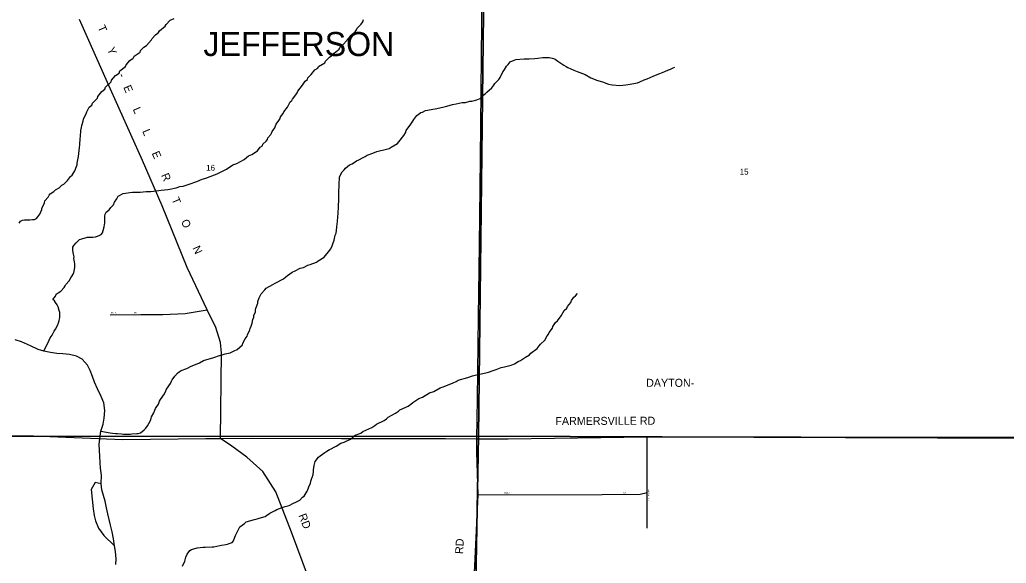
# Model space of a CAD drawing. Extents: x 1312308 to 1684953, y 460642 to 865172.
# Drawn here: x 1455224 to 1464469, y 623895 to 628989 of the extents above; entities that cross this region are included whole.
import ezdxf

# ---------------------------------------------------------------- set-up
doc = ezdxf.new("R2010")
doc.units = 0
for name, color, linetype in [('GM_X_County_Road', 7, 'Continuous'), ('GM_X_County_Road_Text', 7, 'Continuous'), ('GM_X_Minor_River', 7, 'Continuous'), ('GM_X_Section', 7, 'Continuous'), ('GM_X_Section_Text', 7, 'Continuous'), ('GM_X_Township_Subdivision', 7, 'Continuous'), ('GM_X_Township_Subdivision_Text', 7, 'Continuous'), ('GM_X_Township_Text', 7, 'Continuous')]:
    doc.layers.add(name, color=color, linetype=linetype)

msp = doc.modelspace()

# ---------------------------------------------------------------- linework, layer by layer
at = {"layer": 'GM_X_County_Road'}
for points in [[(1459508.2, 625062.6), (1459512.2, 625434.5), (1459523.6, 626204.4), (1459532.8, 626876), (1459543.2, 627687.9), (1459552.6, 628638), (1459557, 629271.5), (1459570.7, 630143.3), (1459577.4, 631061.3), (1459621.4, 632060.4)], [(1458997.4, 620898.3), (1458819.1, 621371.3), (1458583.5, 622020.5), (1458321, 622722.5), (1457980.8, 623622.7), (1457769.3, 624187), (1457623.6, 624565.4), (1457501.7, 624754.6), (1457352.5, 624890.3), (1457210.6, 624993.7), (1457105.9, 625064), (1457115.4, 625863), (1457105.7, 625964.9), (1457061.5, 626103.5), (1456978.7, 626269), (1456791.8, 626665.5), (1456559.2, 627244.6), (1456374.5, 627669.9), (1456047.3, 628401.2), (1455783.7, 628992)], [(1454210.5, 625100.4), (1455352.9, 625087.9), (1456190.5, 625056.2), (1456967.8, 625063.2), (1457105.9, 625064), (1457396.6, 625065.8), (1458239.8, 625063.3), (1459213.3, 625064), (1459508.2, 625062.6), (1459800.2, 625061.2), (1461104, 625081.4), (1462543.4, 625079.9), (1464684.9, 625077), (1465945, 625083.6)], [(1459463.9, 622759.1), (1459465.3, 622835.9), (1459485.3, 623806.4), (1459520.8, 624537.8), (1459507, 624939.2), (1459508.2, 625062.6)]]:
    msp.add_lwpolyline(points, dxfattribs=at)
at = {"layer": 'GM_X_Minor_River'}
for points in [[(1455219.1, 627082), (1455231.6, 627099.8), (1455250, 627111.4), (1455268.2, 627112.9), (1455284.3, 627112.6), (1455318.5, 627113.7), (1455344.7, 627115.1), (1455362.9, 627116.7), (1455381.3, 627126.3), (1455393.7, 627142), (1455410.5, 627165.8), (1455421.1, 627189.6), (1455429.7, 627209.5), (1455432.1, 627223.6), (1455449.1, 627257.3), (1455455.5, 627273.3), (1455460, 627291.2), (1455489.1, 627326.7), (1455499.6, 627344.6), (1455508, 627358.4), (1455542.8, 627379.7), (1455559.3, 627395.4), (1455592, 627412.7), (1455618.8, 627438.2), (1455637.1, 627447.8), (1455672.3, 627483.1), (1455699.4, 627520.7), (1455715.8, 627532.3), (1455741, 627573.9), (1455754.1, 627613.8), (1455760.6, 627629.8), (1455763, 627645.8), (1455772.3, 627691.8), (1455774.7, 627707.8), (1455780.1, 627762), (1455784.9, 627792), (1455785.5, 627816.2), (1455791.1, 627876.3), (1455791.6, 627894.4), (1455797.1, 627950.6), (1455803.8, 627978.6), (1455806.3, 627998.7), (1455819.5, 628038.5), (1455822, 628060.6), (1455847.4, 628108.2), (1455851.9, 628124.2), (1455875.1, 628167.9), (1455897.8, 628187.4), (1455904.3, 628205.4), (1455951.8, 628252.5), (1455956.2, 628268.4), (1455991.7, 628315.8), (1456020.4, 628337.2), (1456026.9, 628357.2), (1456080.5, 628406.2), (1456085, 628422.1), (1456122.4, 628467.4), (1456155.1, 628488.8), (1456161.7, 628508.7), (1456215.1, 628551.6), (1456221.5, 628565.6), (1456256.8, 628606.9), (1456287.6, 628628.3), (1456296.1, 628646.2), (1456351.4, 628685), (1456355.8, 628699), (1456386.9, 628732.4), (1456411.4, 628747.9), (1456459, 628799), (1456465.4, 628812.9), (1456496.5, 628848.4), (1456525.2, 628867.8), (1456533.7, 628885.7), (1456587.2, 628928.6), (1456595.6, 628944.4), (1456634.9, 628983.7), (1456669.5, 629000.9)], [(1457613.3, 627976.4), (1457621.8, 627994.3), (1457626.2, 628010.3), (1457653.3, 628045.8), (1457663.8, 628063.7), (1457668.3, 628079.6), (1457693.3, 628111.2), (1457699.7, 628127.1), (1457733, 628170.5), (1457758.4, 628218.2), (1457774.9, 628231.9), (1457779.3, 628245.8), (1457812.5, 628285.2), (1457825, 628303), (1457829.5, 628319), (1457873.2, 628374.2), (1457898.3, 628413.8), (1457918.9, 628429.4), (1457923.2, 628443.4), (1457956.3, 628474.7), (1457989.6, 628518.2), (1458016.2, 628533.6), (1458024.6, 628549.5), (1458081.9, 628586.3), (1458088.3, 628600.2), (1458125.5, 628637.5), (1458158.3, 628658.8), (1458168.8, 628676.6), (1458218, 628713.6), (1458222.4, 628727.6), (1458251.3, 628753), (1458292.6, 628796.2), (1458311.3, 628817.9), (1458319.9, 628837.8), (1458367.2, 628876.8), (1458379.7, 628894.6), (1458386.1, 628908.5), (1458423.3, 628945.8), (1458438, 628969.6), (1458446.6, 628991.5)], [(1458214.2, 627316.2), (1458213.1, 627352.4), (1458215.9, 627458.9), (1458218.9, 627499.1), (1458221.4, 627517.1), (1458246.7, 627562.8), (1458263.3, 627582.5), (1458275.8, 627596.2), (1458314.9, 627629.5), (1458339.3, 627638.9), (1458378.2, 627666.1), (1458402.6, 627675.6), (1458441.4, 627698.8), (1458461.8, 627706.3), (1458478.2, 627718), (1458533, 627736.7), (1458569.7, 627753.9), (1458608.2, 627763), (1458622.3, 627766.7), (1458685.2, 627783.3), (1458703.6, 627794.9), (1458762.8, 627829.6), (1458777.3, 627845.3), (1458823.1, 627902.5), (1458837.9, 627930.3), (1458846.5, 627950.2), (1458890.3, 628009.5), (1458907.1, 628037.2), (1458915.6, 628055.1), (1458944.7, 628090.6), (1458959, 628100.3), (1458983.6, 628117.8), (1458997.9, 628123.5), (1459026.4, 628136.8), (1459044.6, 628140.4), (1459095.2, 628151.2), (1459115.4, 628154.8), (1459188.3, 628169.1), (1459212.6, 628176.5), (1459226.8, 628180.2), (1459279.5, 628195), (1459313.9, 628200.2), (1459370.6, 628212.9), (1459400.8, 628214.1), (1459441.3, 628225.2), (1459461.5, 628226.7), (1459506.1, 628237.7), (1459538.6, 628251), (1459563.5, 628278.5), (1459590.1, 628296), (1459600.5, 628309.8), (1459647.9, 628350.9), (1459666.6, 628374.5), (1459677.1, 628390.4), (1459714.3, 628427.7), (1459724.8, 628447.5), (1459750.4, 628501.2), (1459764.8, 628514.9), (1459786, 628554.6), (1459800.4, 628568.3), (1459819.2, 628594), (1459857.9, 628611.1), (1459872.1, 628616.8), (1459950.7, 628620.9), (1459981, 628622.2), (1459999.1, 628623.8), (1460049.5, 628626.6), (1460079.8, 628629.8), (1460126.2, 628634.7), (1460150.3, 628634.1), (1460184.6, 628635.3), (1460200.6, 628632.9), (1460224.6, 628624.3), (1460240.5, 628619.9), (1460266.2, 628601.2), (1460286, 628588.6), (1460323.6, 628561.6), (1460343.4, 628551), (1460359.3, 628540.6), (1460415, 628515.1), (1460446.8, 628502.2), (1460522.6, 628474.3), (1460576.1, 628442.8), (1460616.1, 628429.8), (1460630, 628423.4), (1460685.9, 628405.9), (1460741.7, 628384.5), (1460775.8, 628379.6), (1460848.1, 628373.8), (1460904.6, 628378.5), (1460945, 628383.5), (1460959.2, 628387.2), (1461011.8, 628398), (1461036.1, 628405.4), (1461074.9, 628426.6), (1461103.3, 628436), (1461160.3, 628458.7), (1461196.9, 628475.9), (1461221.3, 628483.4), (1461270.1, 628502.3), (1461304.8, 628519.5)], [(1461304.8, 628519.5), (1461323, 628525.1), (1461347.5, 628536.6), (1461361.7, 628544.3)], [(1455450.7, 625882.1), (1455498.7, 625985.1), (1455507.4, 626007), (1455528.1, 626032.6), (1455545.2, 626070.4), (1455557.8, 626088.2), (1455578.8, 626123.9), (1455585.5, 626147.9), (1455594.1, 626169.8), (1455596.5, 626183.8), (1455598.9, 626199.8), (1455598, 626244.1), (1455594.5, 626264.3), (1455583.3, 626298.8), (1455575.7, 626317), (1455558.2, 626337.6), (1455548.6, 626355.9), (1455534.8, 626368.3), (1455559.7, 626397.9), (1455564.2, 626415.9), (1455584.7, 626429.4), (1455607.2, 626445), (1455640.3, 626478.4), (1455648.8, 626494.2), (1455655.2, 626508.2), (1455686.2, 626541.6), (1455701, 626569.4), (1455713.6, 626587.2), (1455724, 626603), (1455730.5, 626621), (1455737.2, 626646.9), (1455739.8, 626669), (1455738.6, 626701.2), (1455737.1, 626719.3), (1455731.9, 626751.7), (1455732.3, 626767.7), (1455726.9, 626792), (1455721.7, 626826.3), (1455722.5, 626856.4), (1455731, 626874.3), (1455751.8, 626898), (1455782.8, 626929.4), (1455805.1, 626936.9), (1455857.8, 626949.7), (1455877.9, 626951.2), (1455910.1, 626950.4), (1455932.4, 626953.9), (1455952.6, 626959.4), (1455973, 626969), (1455987.2, 626974.7), (1455997.7, 626990.5), (1456006.3, 627012.4), (1456015.3, 627048.4), (1456020.3, 627086.5), (1456021.5, 627130.7), (1456019.9, 627146.8), (1456024.4, 627166.8), (1456035, 627186.7), (1456061.6, 627206.1), (1456078.3, 627227.8), (1456103.1, 627253.3), (1456111.8, 627279.3), (1456132.8, 627310.9), (1456147.5, 627336.7), (1456192.4, 627359.8), (1456214.6, 627363.2), (1456255.1, 627370.3), (1456281.3, 627371.7), (1456351.8, 627373.9), (1456408.3, 627378.6), (1456452.6, 627379.5), (1456527.3, 627389.7), (1456547.5, 627391.3), (1456612.1, 627397.7), (1456630.3, 627401.3), (1456688.9, 627411.9), (1456725.5, 627425.1), (1456755.8, 627430.4), (1456810.7, 627449.2), (1456883.7, 627473.5), (1456932.6, 627494.4), (1456969.1, 627503.6), (1457048.3, 627533.8), (1457072.8, 627545.3), (1457160.4, 627587.4), (1457221.9, 627628.1), (1457258.4, 627641.3), (1457327.8, 627677.8), (1457369, 627713), (1457399.5, 627724.3), (1457450.7, 627761.2), (1457477.8, 627794.8), (1457498.2, 627808.3), (1457502.6, 627822.3), (1457533.6, 627851.7), (1457544.1, 627867.5), (1457548.4, 627881.5), (1457575.4, 627913), (1457583.8, 627926.9), (1457588.2, 627940.9), (1457613.3, 627976.4)], [(1455982.9, 625132), (1456070.1, 625116.2), (1456094.2, 625113.6), (1456122.3, 625110.9), (1456138.4, 625110.5), (1456178.5, 625107.5), (1456194.6, 625105.1), (1456257, 625105.6), (1456275.2, 625107.2), (1456319.5, 625110.1), (1456333.6, 625111.8), (1456353.9, 625117.3), (1456390.9, 625146.6), (1456405.4, 625162.3), (1456422.1, 625184), (1456432.6, 625203.9), (1456447.5, 625233.7), (1456454.1, 625253.7), (1456458.4, 625267.6), (1456481.6, 625305.3), (1456490.2, 625329.2), (1456494.7, 625345.2), (1456523.9, 625386.7), (1456534.6, 625412.6), (1456543.1, 625428.5), (1456578.7, 625481.9), (1456591.5, 625509.8), (1456600, 625527.6), (1456635.6, 625579.1), (1456646.2, 625600.9), (1456652.6, 625614.9), (1456675.6, 625648.5), (1456702.5, 625678), (1456716.9, 625687.7), (1456737.3, 625701.3), (1456788.1, 625720.1), (1456831, 625743.2), (1456855.4, 625750.7), (1456908.3, 625773.5), (1456947.1, 625796.7), (1456977.6, 625806), (1457034.3, 625820.7), (1457060.7, 625828.1), (1457077, 625835.8), (1457129.7, 625850.5), (1457150, 625858.1), (1457194.5, 625867.1), (1457233.2, 625886.2), (1457259.7, 625897.7), (1457311.1, 625940.6), (1457315.6, 625956.6), (1457336.8, 625998.3), (1457353.5, 626022.1), (1457357.9, 626036), (1457379.2, 626081.8), (1457381.6, 626095.8), (1457392.1, 626115.7), (1457401, 626145.6), (1457407.9, 626179.6), (1457416.5, 626201.5), (1457418.9, 626215.5), (1457431.9, 626251.4), (1457434.4, 626269.5), (1457436.7, 626283.5), (1457449.7, 626317.4), (1457454.1, 626333.3), (1457456.5, 626347.4), (1457467.4, 626381.3), (1457486.6, 626421), (1457519.8, 626458.4), (1457532.2, 626472.2), (1457595.5, 626508.9), (1457618, 626520.4), (1457695.5, 626560.7), (1457718.1, 626578.3), (1457732.5, 626592), (1457777.6, 626623.1), (1457806.1, 626634.4), (1457853, 626659.4), (1457881.4, 626666.8), (1457922.2, 626687.9), (1457946.6, 626695.3), (1458003.4, 626716.1), (1458021.9, 626729.7), (1458075.1, 626762.6), (1458089.6, 626778.3), (1458116.7, 626813.8), (1458139.5, 626841.4), (1458152.3, 626869.3), (1458156.8, 626887.3), (1458171.8, 626923.1), (1458181.1, 626969.1), (1458187.6, 626989.1), (1458195.1, 627045.2), (1458199.9, 627075.2), (1458200.4, 627093.3), (1458205.7, 627143.5), (1458206.4, 627169.6), (1458208.8, 627183.6), (1458211.9, 627225.8), (1458214.2, 627316.2)], [(1458125.2, 624961.3), (1458141.4, 624966.9), (1458170.1, 624984.3), (1458190.4, 624991.9), (1458233.4, 625021), (1458263.8, 625030.3), (1458322.9, 625057), (1458366.1, 625094.2), (1458419, 625115), (1458437.5, 625128.7), (1458523, 625166.8), (1458551.7, 625186.2), (1458568.1, 625197.9), (1458639.4, 625232.3), (1458662, 625249.9), (1458676.5, 625263.6), (1458745.8, 625300.2), (1458772.5, 625319.6), (1458786.9, 625333.3), (1458862.3, 625367.7), (1458889, 625387.2), (1458907.4, 625400.8), (1458962.7, 625437.7), (1458999.4, 625452.8), (1459062.8, 625491.5), (1459103.4, 625504.6), (1459162.6, 625539.4), (1459201.2, 625552.5), (1459286.6, 625584.6), (1459315.1, 625598), (1459331.5, 625609.7), (1459422.8, 625635.6), (1459465.5, 625652.7), (1459516.1, 625663.5), (1459546.4, 625668.8), (1459591, 625679.8), (1459617.3, 625685.1), (1459660, 625702.2), (1459688.4, 625709.6), (1459735.1, 625728.5), (1459767.5, 625735.8), (1459828.3, 625750.4), (1459860.8, 625763.7), (1459893.6, 625785), (1459916, 625794.5), (1459963.1, 625827.5), (1459999.9, 625848.8), (1460012.3, 625862.5), (1460071.9, 625907.3), (1460090.6, 625933), (1460103.1, 625946.8), (1460144.4, 625986), (1460167.5, 626025.7), (1460180.1, 626043.5), (1460186.5, 626057.4), (1460215.7, 626096.9), (1460220.1, 626112.9), (1460243.2, 626150.5), (1460261.8, 626168.2), (1460297.2, 626213.6), (1460326.7, 626265.1), (1460349.4, 626286.7), (1460355.8, 626300.6), (1460389, 626340), (1460393.4, 626356), (1460416.4, 626387.7), (1460430.8, 626401.4), (1460449.5, 626423)], [(1455967.5, 625010), (1455982.9, 625132), (1456006.8, 625197.6), (1456014.4, 625255.7), (1456020.3, 625325.8), (1456010.3, 625398.3), (1455985.8, 625459.3), (1455951.6, 625530.5), (1455925.1, 625593.5), (1455904.5, 625646.3), (1455883.9, 625701.1), (1455859.1, 625752), (1455808.4, 625807.7), (1455754.9, 625837.3), (1455691, 625851.2), (1455628.9, 625858.9), (1455572.7, 625860.5), (1455510.6, 625870.3), (1455450.7, 625882.1), (1455396.9, 625899.7), (1455325.4, 625931.8), (1455240.1, 625970.4), (1455182.3, 625990.1)], [(1456125.7, 623882.8), (1456127.1, 623935), (1456121, 624005.5), (1456110.4, 624058), (1456102.1, 624122.5), (1456089.9, 624191.1), (1456075.5, 624251.8), (1456062.9, 624306.4), (1456048.2, 624359), (1456035.7, 624413.6), (1456025.4, 624478.2), (1456008.7, 624530.8), (1455994.1, 624583.5), (1455987.5, 624637.9), (1455989.8, 624720.2), (1455981.5, 624784.7), (1455976.9, 624837), (1455974.6, 624899.3), (1455972, 624951.6), (1455967.5, 625010)], [(1456748.3, 623866.5), (1456771.7, 623916.2), (1456778.3, 623938.2), (1456780.7, 623952.2), (1456791.5, 623980.1), (1456818.6, 624015.7), (1456832.9, 624023.3), (1456887.7, 624040.1), (1456942.1, 624044.8), (1456962.3, 624046.3), (1457026.8, 624048.8), (1457042.9, 624050.4), (1457099.5, 624061.1), (1457113.7, 624064.8), (1457154.2, 624071.8), (1457170.3, 624073.4), (1457186.6, 624079.1), (1457215, 624090.4), (1457225.5, 624106.3), (1457240.4, 624138.1), (1457244.9, 624156.1), (1457270.3, 624205.8), (1457278.9, 624223.7), (1457287.3, 624237.5), (1457330.3, 624268.7), (1457346.9, 624284.4), (1457423.9, 624304.6), (1457450.2, 624312), (1457466.5, 624317.6), (1457523.3, 624334.4), (1457537.6, 624344.1), (1457566.3, 624365.5), (1457617.3, 624390.4), (1457633.6, 624400), (1457684.4, 624416.9), (1457710.9, 624428.3), (1457747.3, 624437.5), (1457788.1, 624458.6), (1457812.5, 624468.1), (1457847.2, 624487.4), (1457872.1, 624512.9), (1457888.5, 624524.6), (1457917.8, 624570.1), (1457922.2, 624584.1), (1457937.2, 624619.9), (1457947.9, 624643.8), (1457952.4, 624663.8), (1457972.2, 624725.7), (1457976.9, 624753.7), (1457977.3, 624769.8), (1457982.4, 624809.9), (1457986.8, 624823.9), (1457993.5, 624849.9), (1458024.7, 624889.3), (1458039.1, 624903.1), (1458084.2, 624932.2), (1458100.6, 624945.8), (1458125.2, 624961.3)], [(1455987.5, 624637.9), (1455931.8, 624652.6), (1455894.3, 624587.1), (1455910.7, 624406.1), (1455921.5, 624343.6), (1455934.6, 624293.2), (1455961.3, 624224.4), (1456012.1, 624155.1), (1456110.4, 624058)]]:
    msp.add_lwpolyline(points, dxfattribs=at)
at = {"layer": 'GM_X_Section'}
for points in [[(1454281.7, 630438.2), (1459585.8, 630367.6), (1459521.5, 625085.3), (1454204, 625082.2)], [(1459585.8, 630367.6), (1464768, 630305.4), (1464682.6, 625067.6), (1459521.5, 625085.3)], [(1454204, 625082.2), (1459521.5, 625085.3), (1459424.8, 619777.8), (1454142, 619813.9)], [(1459521.5, 625085.3), (1464682.6, 625067.6), (1464595.6, 619745.9), (1459424.8, 619777.8)]]:
    msp.add_lwpolyline(points, close=True, dxfattribs=at)
at = {"layer": 'GM_X_Township_Subdivision'}
for points in [[(1456070.4, 626222.8), (1456357.2, 626226.6), (1456565, 626226.6), (1456774.7, 626236.2), (1456978.7, 626269)], [(1461103.8, 624491.2), (1461104.2, 624559.6), (1461104, 625081.4)], [(1459520.8, 624537.8), (1460681.8, 624538.9), (1461038.3, 624543.7), (1461104.2, 624559.6)], [(1461104, 624222.9), (1461103.4, 624429.4), (1461103.8, 624491.2)]]:
    msp.add_lwpolyline(points, dxfattribs=at)

# ---------------------------------------------------------------- texts
at = {"layer": 'GM_X_County_Road_Text'}
for s, rotation, p in [('T', 293.24755, (1455951.6, 628918.9)), ('Y', 293.25146, (1456040.2, 628712.7)), ('-', 293.25408, (1456144.4, 628470.1)), ('E', 293.24755, (1456193, 628356.9)), ('L', 293.24755, (1456281.6, 628150.7)), ('L', 293.24755, (1456370.2, 627944.6)), ('E', 293.25215, (1456458.8, 627738.3)), ('R', 293.25036, (1456547.4, 627532.2)), ('T', 293.24755, (1456644.6, 627305.8)), ('O', 293.31607, (1456733.3, 627099.2)), ('N', 294.65121, (1456840.9, 626849.8)), ('DAYTON-', 0.00001, (1461093.7, 625548.5)), ('FARMERSVILLE RD', 0.14897, (1460243.4, 625190.8)), ('RD', 291.07484, (1457834.3, 624344)), ('RD', 87.03883, (1459378.6, 623980.1))]:
    msp.add_text(s, height=75, rotation=rotation, dxfattribs=at).set_placement(p)
at = {"layer": 'GM_X_Section_Text'}
for s, p in [('16', (1456970.9, 627573.6)), ('15', (1461971.5, 627536.7))]:
    msp.add_text(s, height=55.25, rotation=0.00001, dxfattribs=at).set_placement(p)
at = {"layer": 'GM_X_Township_Subdivision_Text'}
for s, rotation, p in [('MCLIN', 0.00001, (1456077.7, 626236.2)), ('DR', 0.00001, (1456293.3, 626236.2)), ('ELLEN', 0.00001, (1459764.9, 624550.9)), ('DR', 0.00001, (1460882.5, 624550.9)), ('BRIDGET DR', 270, (1461111.9, 624590))]:
    msp.add_text(s, height=12.5, rotation=rotation, dxfattribs=at).set_placement(p)
at = {"layer": 'GM_X_Township_Text'}
msp.add_text('JEFFERSON', height=225, rotation=0.00001, dxfattribs=at).set_placement((1456945, 628648.4))

doc.saveas('drawing.dxf')
